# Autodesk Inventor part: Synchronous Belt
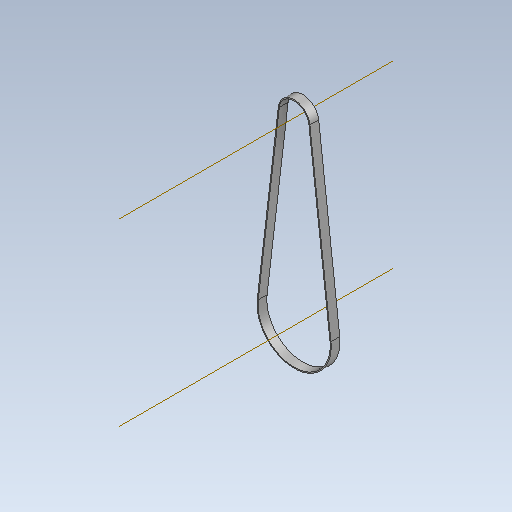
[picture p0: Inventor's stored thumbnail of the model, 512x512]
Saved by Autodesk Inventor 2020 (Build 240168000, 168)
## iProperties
Created: 2019-09
Part Number: Synchronous Belt
Material: Rubber
Document SubType Name: Modeling
Designer: user
Density: 1 g/cm^3
Appearance: Rubber - Black - Version 1.1
CustomPartVersion: 1
Author: user
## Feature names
1. Belt
## Parameters: da_B = 9.398 mm, da_pb = 5.08 mm, da_L = 558.8 mm, da_a = 0.254 mm, da_S = 2.5654 mm, da_Beta = 25 deg, da_Ht = 1.27 mm, d0 = 9.398 mm, d2 = 0, da_H = 2.286 mm, d4 = 0.254 mm, da_a2 = 0.762 mm, d5 = 0.762 mm, d6 = 0, d7 = 0, d8 = 0, d9 = 0, d10 = 0, d11 = 0
